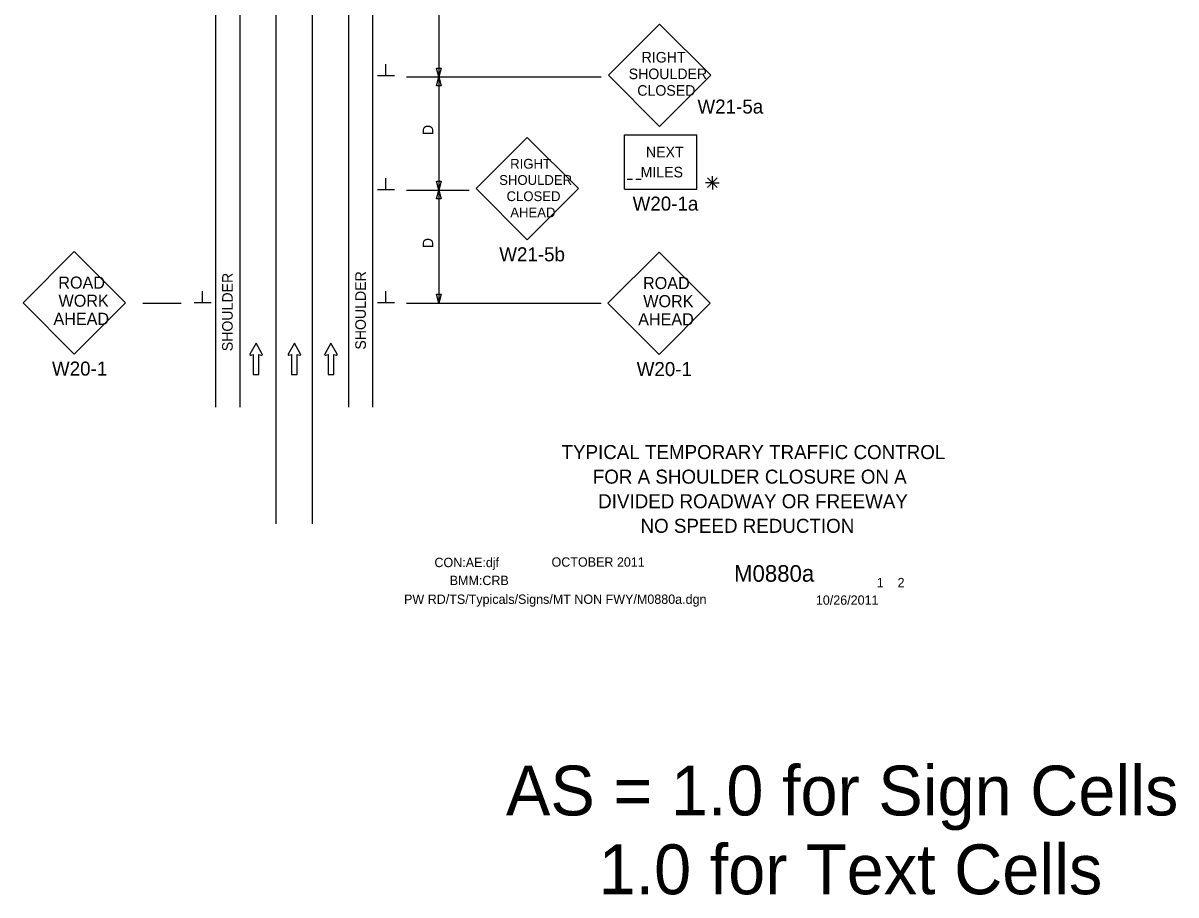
# Model space of a CAD drawing. Extents: x 16738 to 18471, y 7027 to 8193.
# Drawn here: x 16818 to 17582, y 7027 to 7605 of the extents above; entities that cross this region are included whole.
import ezdxf

# ---------------------------------------------------------------- set-up
doc = ezdxf.new("R2010")
doc.units = 0
for name, color, linetype in [('ALI_LEGAL_EX', 7, 'Continuous'), ('BORDER', 7, 'Continuous'), ('BORDER_SIGNAL_WO', 7, 'Continuous'), ('MT_SCRATCH_LEVEL_E', 7, 'Continuous'), ('PAVT_EDGE_EX', 7, 'Continuous'), ('TRAFFIC_SIGNS_PR', 7, 'Continuous'), ('TYPICAL_TEXT_DIMEN_PR', 7, 'Continuous')]:
    doc.layers.add(name, color=color, linetype=linetype)

msp = doc.modelspace()

# ---------------------------------------------------------------- linework, layer by layer
at = {"layer": 'ALI_LEGAL_EX'}
for points in [[(16985.65, 7553.48), (16985.65, 7528.48)], [(17009.65, 7553.48), (17009.65, 7528.48)], [(16985.65, 7453.48), (16985.65, 7428.48)], [(17009.65, 7453.48), (17009.65, 7428.48)]]:
    msp.add_lwpolyline(points, dxfattribs=at)
at = {"layer": 'MT_SCRATCH_LEVEL_E'}
for p, q in [((16972.46, 7392.78), (16968.34, 7385.54)), ((16972.46, 7392.78), (16968.34, 7385.54)), ((16976.6, 7385.54), (16972.46, 7392.78)), ((16976.6, 7385.54), (16972.46, 7392.78)), ((16997.88, 7392.78), (16993.77, 7385.54)), ((16997.88, 7392.78), (16993.77, 7385.54)), ((17002.03, 7385.54), (16997.88, 7392.78)), ((17002.03, 7385.54), (16997.88, 7392.78)), ((17022.09, 7392.78), (17017.98, 7385.54)), ((17022.09, 7392.78), (17017.98, 7385.54)), ((17026.24, 7385.54), (17022.09, 7392.78)), ((17026.24, 7385.54), (17022.09, 7392.78)), ((16968.83, 7384.86), (16970.6, 7385.17)), ((16968.83, 7384.86), (16970.6, 7385.17)), ((16970.6, 7385.17), (16970.6, 7371.92)), ((16970.6, 7385.17), (16970.6, 7371.92)), ((16974.35, 7371.92), (16974.35, 7385.17)), ((16974.35, 7385.17), (16976.12, 7384.86)), ((16974.35, 7371.92), (16974.35, 7385.17)), ((16974.35, 7385.17), (16976.12, 7384.86)), ((16994.25, 7384.86), (16996.03, 7385.17)), ((16994.25, 7384.86), (16996.03, 7385.17)), ((16996.03, 7385.17), (16996.03, 7371.92)), ((16996.03, 7385.17), (16996.03, 7371.92)), ((16999.77, 7371.92), (16999.77, 7385.17)), ((16999.77, 7385.17), (17001.55, 7384.86)), ((16999.77, 7371.92), (16999.77, 7385.17)), ((16999.77, 7385.17), (17001.55, 7384.86)), ((17018.47, 7384.86), (17020.24, 7385.17)), ((17018.47, 7384.86), (17020.24, 7385.17)), ((17020.24, 7385.17), (17020.24, 7371.92)), ((17020.24, 7385.17), (17020.24, 7371.92)), ((17023.98, 7371.92), (17023.98, 7385.17)), ((17023.98, 7385.17), (17025.76, 7384.86)), ((17023.98, 7371.92), (17023.98, 7385.17)), ((17023.98, 7385.17), (17025.76, 7384.86)), ((16970.6, 7371.92), (16974.35, 7371.92)), ((16970.6, 7371.92), (16974.35, 7371.92)), ((16996.03, 7371.92), (16999.77, 7371.92)), ((16996.03, 7371.92), (16999.77, 7371.92)), ((17020.24, 7371.92), (17023.98, 7371.92)), ((17020.24, 7371.92), (17023.98, 7371.92))]:
    msp.add_line(p, q, dxfattribs=at)
for centre, start, end in [((16968.75, 7385.32), 150.42484, 279.96381), ((16968.75, 7385.32), 150.42484, 279.96381), ((16976.19, 7385.32), 260.03619, 29.77312), ((16976.19, 7385.32), 260.03619, 29.77312), ((16994.18, 7385.32), 150.42484, 279.96381), ((16994.18, 7385.32), 150.42484, 279.96381), ((17001.62, 7385.32), 260.03619, 29.77312), ((17001.62, 7385.32), 260.03619, 29.77312), ((17018.39, 7385.32), 150.42484, 279.96381), ((17018.39, 7385.32), 150.42484, 279.96381), ((17025.83, 7385.32), 260.03619, 29.77312), ((17025.83, 7385.32), 260.03619, 29.77312)]:
    msp.add_arc(centre, 0.463, start, end, dxfattribs=at)
at = {"layer": 'PAVT_EDGE_EX'}
for p, q in [((16985.65, 8140.15), (16985.65, 7272.98)), ((17009.65, 8140.15), (17009.65, 7272.98)), ((16985.65, 8025.46), (16985.65, 7272.98)), ((17009.65, 8025.46), (17009.65, 7272.98)), ((16945.65, 7870.68), (16945.65, 7350.36)), ((16961.65, 7870.6), (16961.65, 7350.36)), ((17033.65, 7870.35), (17033.65, 7350.36)), ((17049.65, 7870.6), (17049.65, 7350.36))]:
    msp.add_line(p, q, dxfattribs=at)
at = {"layer": 'TRAFFIC_SIGNS_PR'}
for p, q in [((17239.93, 7604.31), (17205.99, 7570.37)), ((17273.88, 7570.37), (17239.93, 7604.31)), ((17205.99, 7570.37), (17239.93, 7536.43)), ((17239.93, 7536.43), (17273.88, 7570.37)), ((17152.2, 7529.22), (17118.26, 7495.28)), ((17186.14, 7495.28), (17152.2, 7529.22)), ((17216.59, 7494.96), (17216.59, 7530.96)), ((17216.59, 7530.96), (17264.59, 7530.96)), ((17264.59, 7494.96), (17264.59, 7530.96)), ((17118.26, 7495.28), (17152.2, 7461.34)), ((17152.2, 7461.34), (17186.14, 7495.28)), ((17216.59, 7494.96), (17264.59, 7494.96)), ((17218.44, 7501.56), (17221.94, 7501.56)), ((17224.24, 7501.56), (17227.74, 7501.56)), ((16852.02, 7453.45), (16818.08, 7419.51)), ((16885.96, 7419.51), (16852.02, 7453.45)), ((17239.5, 7453.16), (17205.55, 7419.22)), ((17273.44, 7419.22), (17239.5, 7453.16)), ((16818.08, 7419.51), (16852.02, 7385.57)), ((16852.02, 7385.57), (16885.96, 7419.51)), ((17205.55, 7419.22), (17239.5, 7385.28)), ((17239.5, 7385.28), (17273.44, 7419.22))]:
    msp.add_line(p, q, dxfattribs=at)
at = {"layer": 'TYPICAL_TEXT_DIMEN_PR'}
for p, q in [((17093.65, 7644.32), (17093.65, 7569.32)), ((17058.58, 7569.94), (17058.58, 7577.73)), ((17093.65, 7569.32), (17092.08, 7575.18)), ((17092.08, 7575.18), (17093.65, 7575.18)), ((17093.65, 7575.18), (17095.22, 7575.18)), ((17095.22, 7575.18), (17093.65, 7569.32)), ((17064.21, 7569.94), (17052.96, 7569.94)), ((17072.13, 7569.32), (17201.23, 7569.32)), ((17092.08, 7563.46), (17093.65, 7569.32)), ((17093.65, 7563.46), (17092.08, 7563.46)), ((17093.65, 7569.32), (17093.65, 7494.32)), ((17093.65, 7569.32), (17095.22, 7563.46)), ((17095.22, 7563.46), (17093.65, 7563.46)), ((17271.68, 7502.29), (17278.06, 7495.92)), ((17278.06, 7502.29), (17271.68, 7495.92)), ((17274.87, 7499.1), (17274.87, 7503.56)), ((17058.58, 7494.33), (17058.58, 7502.12)), ((17093.65, 7494.32), (17092.08, 7500.18)), ((17092.08, 7500.18), (17093.65, 7500.18)), ((17093.65, 7500.18), (17095.22, 7500.18)), ((17095.22, 7500.18), (17093.65, 7494.32)), ((17274.87, 7499.1), (17270.34, 7499.1)), ((17274.87, 7499.1), (17278.06, 7499.1)), ((17274.87, 7499.1), (17279.35, 7499.1)), ((17274.87, 7499.1), (17274.87, 7494.6)), ((17064.21, 7494.33), (17052.96, 7494.33)), ((17072.13, 7494.32), (17113.63, 7494.32)), ((17092.08, 7488.46), (17093.65, 7494.32)), ((17093.65, 7488.46), (17092.08, 7488.46)), ((17093.65, 7494.32), (17093.65, 7419.32)), ((17093.65, 7494.32), (17095.22, 7488.46)), ((17095.22, 7488.46), (17093.65, 7488.46)), ((16937.08, 7419.45), (16937.08, 7427.24)), ((17058.58, 7419.45), (17058.58, 7427.24)), ((16897.39, 7419.32), (16922.79, 7419.32)), ((16942.7, 7419.45), (16931.45, 7419.45)), ((17064.21, 7419.45), (17052.96, 7419.45)), ((17072.13, 7419.32), (17201.23, 7419.32)), ((17093.65, 7419.32), (17092.08, 7425.18)), ((17092.08, 7425.18), (17093.65, 7425.18)), ((17093.65, 7425.18), (17095.22, 7425.18)), ((17095.22, 7425.18), (17093.65, 7419.32))]:
    msp.add_line(p, q, dxfattribs=at)

# ---------------------------------------------------------------- texts
at = {"layer": 'BORDER'}
for s, p in [('TYPICAL TEMPORARY TRAFFIC CONTROL', (17174.93, 7315.95)), ('FOR A SHOULDER CLOSURE ON A', (17195.63, 7299.65)), ('DIVIDED ROADWAY OR FREEWAY', (17199.21, 7283.35)), ('NO SPEED REDUCTION', (17227.26, 7267.05))]:
    msp.add_text(s, height=9.3, dxfattribs=at).set_placement(p)
at = {"layer": 'BORDER_SIGNAL_WO'}
for s, height, p in [('CON:AE:djf', 6.2, (17090.69, 7244.31)), ('    OCTOBER 2011    ', 6.2, (17159.08, 7244.59)), ('    M0880a   ', 11, (17272.86, 7234.63)), ('BMM:CRB   ', 6.2, (17100.81, 7232.42)), (' 1    2 ', 6.2, (17381.45, 7230.95)), ('PW RD/TS/Typicals/Signs/MT NON FWY/M0880a.dgn     ', 6.2, (17070.55, 7219.96)), ('10/26/2011    ', 6.2, (17343.46, 7219.38)), ('AS = 1.0 for Sign Cells', 33.0301, (17138.06, 7079.7)), ('     1.0 for Text Cells', 33.0301, (17138.06, 7027.47))]:
    msp.add_text(s, height=height, dxfattribs=at).set_placement(p)
at = {"layer": 'TRAFFIC_SIGNS_PR'}
for s, height, p in [('RIGHT', 7, (17227.99, 7578.82)), ('SHOULDER', 7, (17219.42, 7567.82)), ('CLOSED', 7, (17225.13, 7556.82)), ('W21-5a', 9.3, (17265, 7544.99)), ('NEXT', 7, (17230.84, 7515.97)), ('RIGHT', 6.5, (17140.88, 7508.45)), ('SHOULDER', 6.5, (17133.61, 7497.7)), ('   MILES', 7, (17219.51, 7502.67)), ('CLOSED', 6.5, (17138.49, 7486.95)), ('W20-1a', 9.3, (17222.02, 7480.66)), ('AHEAD', 6.5, (17140.94, 7476.2)), ('W21-5b', 9.3, (17133.65, 7447.04)), ('ROAD', 8, (16841.45, 7428.93)), ('ROAD', 8, (17228.92, 7428.64)), ('WORK', 8, (16841.59, 7416.93)), ('WORK', 8, (17229.06, 7416.64)), ('AHEAD', 8, (16838.23, 7404.93)), ('AHEAD', 8, (17225.7, 7404.64)), ('W20-1', 9.3, (16837.24, 7371.28)), ('W20-1', 9.3, (17224.71, 7370.98))]:
    msp.add_text(s, height=height, dxfattribs=at).set_placement(p)
at = {"layer": 'TYPICAL_TEXT_DIMEN_PR'}
for s, p in [('D', (17089.92, 7530.74)), ('D', (17089.92, 7455.74)), ('SHOULDER', (16957.01, 7387.43)), ('SHOULDER', (17045.24, 7388.49))]:
    msp.add_text(s, height=7, rotation=90, dxfattribs=at).set_placement(p)

doc.saveas('drawing.dxf')
